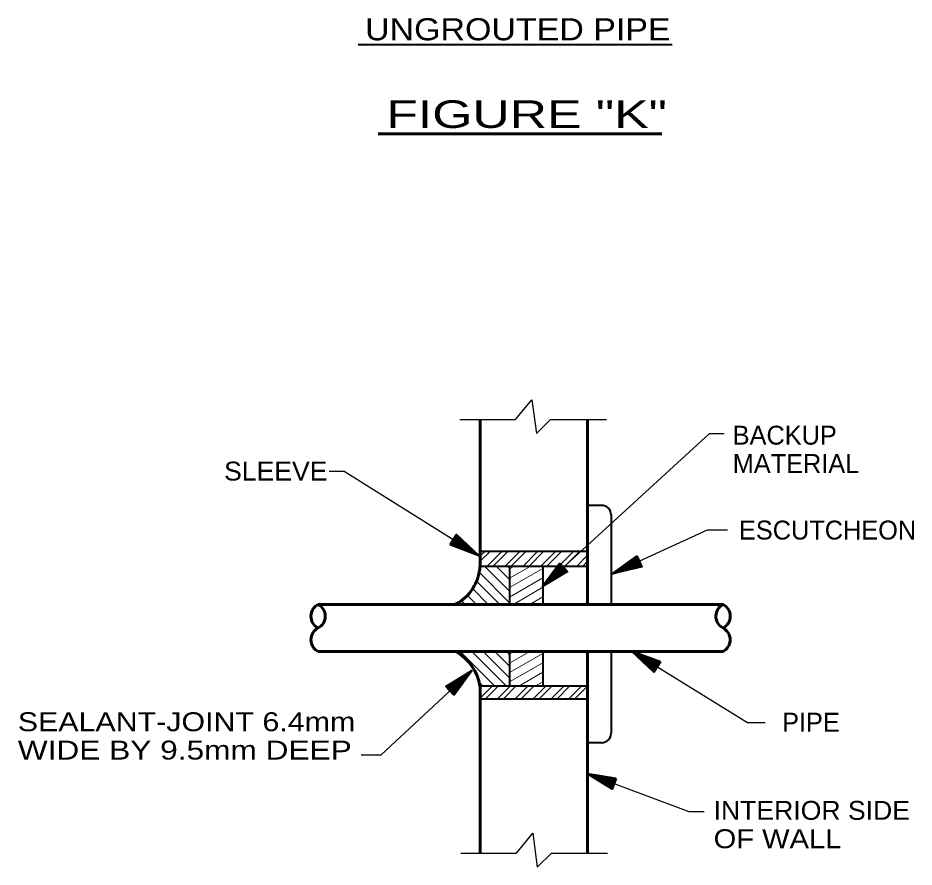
# Model space of a CAD drawing. Extents: x 55 to 190, y 198 to 264.
# Drawn here: x 88.91 to 100.94, y 236.28 to 247.68 of the extents above; entities that cross this region are included whole.
import ezdxf
from ezdxf.enums import TextEntityAlignment as Align

# ---------------------------------------------------------------- set-up
doc = ezdxf.new("R2010")
doc.units = 0
doc.header["$LTSCALE"] = 0.1
doc.layers.add('2', color=7, linetype='Continuous', lineweight=40)

msp = doc.modelspace()

# ---------------------------------------------------------------- linework, layer by layer
at = {"layer": '2'}
for p, q in [((97.6914, 247.3229), (93.4758, 247.3229)), ((96.7418, 241.1372), (96.5548, 241.1372)), ((96.8704, 241.0086), (96.8704, 239.8093)), ((95.094, 240.4649), (94.7625, 240.6959)), ((95.094, 240.4649), (94.7834, 240.7292)), ((95.094, 240.4649), (94.7201, 240.6284)), ((95.094, 240.4649), (94.7315, 240.6477)), ((95.094, 240.4649), (94.7416, 240.6628)), ((94.7514, 240.6789), (95.094, 240.4649)), ((96.5548, 240.5189), (95.1096, 240.5189)), ((95.9504, 240.0479), (96.1941, 240.3482)), ((95.9504, 240.0479), (96.2089, 240.3326)), ((96.8805, 240.2175), (97.2226, 240.4398)), ((96.8805, 240.2175), (97.2326, 240.4194)), ((96.8805, 240.2175), (97.2395, 240.4027)), ((97.2477, 240.3858), (96.8805, 240.2175)), ((96.8805, 240.2175), (97.2556, 240.3673)), ((96.8805, 240.2175), (97.272, 240.3316)), ((96.5548, 240.318), (95.1096, 240.318)), ((95.5067, 240.3173), (95.5067, 239.8032)), ((95.9504, 240.0479), (96.22, 240.3199)), ((96.2322, 240.3069), (95.9504, 240.0479)), ((95.9504, 240.0479), (96.2449, 240.2924)), ((95.9504, 240.0479), (96.2703, 240.2649)), ((95.9528, 240.3173), (95.9528, 239.8032)), ((95.5067, 239.1745), (95.5067, 238.7118)), ((95.9528, 239.1745), (95.9528, 238.7075)), ((96.8704, 239.1766), (96.8704, 238.0781)), ((97.489, 238.9679), (97.1453, 239.1801)), ((97.1453, 239.1801), (97.5086, 238.9988)), ((97.1453, 239.1801), (97.4572, 238.9173)), ((97.1453, 239.1801), (97.4779, 238.9507)), ((97.1453, 239.1801), (97.4985, 238.984)), ((97.1453, 239.1801), (97.5199, 239.0184)), ((95.0011, 238.9203), (94.6654, 238.6885)), ((95.0011, 238.9203), (94.6921, 238.6596)), ((94.7058, 238.6448), (95.0011, 238.9203)), ((95.0011, 238.9203), (94.7188, 238.6311)), ((95.0011, 238.9203), (94.7307, 238.6176)), ((95.0011, 238.9203), (94.7463, 238.6014)), ((96.5548, 238.7075), (95.1096, 238.7075)), ((95.1096, 238.5382), (96.5548, 238.5382)), ((96.7418, 237.9495), (96.5548, 237.9495)), ((96.9117, 237.3986), (96.5529, 237.5317)), ((96.5529, 237.5317), (96.9241, 237.4312)), ((96.5529, 237.5317), (96.8916, 237.3457)), ((96.5529, 237.5317), (96.9048, 237.3807)), ((96.5529, 237.5317), (96.9178, 237.4153)), ((96.5529, 237.5317), (96.931, 237.4513))]:
    msp.add_line(p, q, dxfattribs=at)
at = {"layer": '2', "lineweight": 60}
for p, q in [((93.7425, 246.1291), (97.5506, 246.1291)), ((95.1109, 242.2895), (95.1109, 240.318)), ((96.5548, 242.2895), (96.5548, 239.8066)), ((98.3722, 239.8066), (92.9366, 239.8066)), ((92.9366, 239.1737), (98.3722, 239.1737)), ((96.5548, 239.1737), (96.5548, 236.467)), ((95.1109, 236.467), (95.1109, 238.7075))]:
    msp.add_line(p, q, dxfattribs=at)
at = {"layer": '2', "lineweight": 13}
for p, q in [((95.1091, 240.4525), (95.176, 240.5194)), ((95.1104, 240.3855), (95.2443, 240.5189)), ((95.2033, 240.318), (95.4041, 240.5189)), ((95.2832, 240.318), (95.4842, 240.5189)), ((95.4432, 240.318), (95.6441, 240.5189)), ((95.5234, 240.318), (95.7242, 240.5189)), ((95.6832, 240.318), (95.884, 240.5189)), ((95.7636, 240.318), (95.9642, 240.5189)), ((95.9235, 240.318), (96.124, 240.5189)), ((96.0036, 240.318), (96.2044, 240.5189)), ((96.1634, 240.318), (96.3643, 240.5189)), ((96.2436, 240.318), (96.4444, 240.5189)), ((96.4034, 240.318), (96.5548, 240.4694)), ((96.4836, 240.318), (96.5548, 240.3892)), ((95.5067, 239.8302), (95.0974, 240.2395)), ((95.5067, 239.9852), (95.1739, 240.318)), ((95.5067, 240.1405), (95.3297, 240.3175)), ((95.5067, 240.2958), (95.485, 240.3173)), ((95.5067, 240.1585), (95.7816, 240.3173)), ((95.5067, 240.2852), (95.562, 240.3173)), ((95.5067, 240.0318), (95.9528, 240.2895)), ((95.3774, 239.8048), (95.0617, 240.1199)), ((95.5067, 239.9053), (95.9528, 240.1625)), ((95.2207, 239.8061), (95.0083, 240.0185)), ((95.5496, 239.8032), (95.9528, 240.0363)), ((94.9072, 239.809), (94.8566, 239.8593)), ((95.0638, 239.8077), (94.9395, 239.9318)), ((95.7692, 239.8032), (95.9528, 239.9095)), ((95.3083, 238.7097), (94.8455, 239.1724)), ((95.4618, 238.7112), (95.0001, 239.1729)), ((95.5067, 238.8216), (95.1546, 239.1735)), ((95.5067, 238.9766), (95.3094, 239.1743)), ((95.5067, 239.1317), (95.4639, 239.1745)), ((95.5067, 239.0181), (95.7777, 239.1745)), ((95.5067, 239.1452), (95.5581, 239.1745)), ((95.5067, 238.8917), (95.9528, 239.1491)), ((95.5067, 238.765), (95.9528, 239.0224)), ((95.6319, 238.7104), (95.9528, 238.8957)), ((95.1546, 238.7078), (95.0948, 238.7676)), ((95.8475, 238.7083), (95.9528, 238.7692)), ((95.1096, 238.544), (95.2731, 238.7075)), ((95.1109, 238.7051), (95.113, 238.7075)), ((95.1837, 238.5382), (95.353, 238.7075)), ((95.3438, 238.5382), (95.5131, 238.7075)), ((95.4237, 238.5382), (95.593, 238.7075)), ((95.5837, 238.5382), (95.7531, 238.7075)), ((95.6639, 238.5382), (95.8332, 238.7075)), ((95.8237, 238.5382), (95.993, 238.7075)), ((95.9039, 238.5382), (96.0732, 238.7075)), ((96.0639, 238.5382), (96.2333, 238.7075)), ((96.1439, 238.5382), (96.3132, 238.7075)), ((96.3039, 238.5382), (96.4733, 238.7075)), ((96.3838, 238.5382), (96.5532, 238.7075)), ((96.5439, 238.5382), (96.5548, 238.5488))]:
    msp.add_line(p, q, dxfattribs=at)
at = {"layer": '2', "lineweight": 25}
for points in [[(94.8403, 242.2895), (95.5845, 242.2895), (95.8065, 242.5564), (95.8663, 242.1013), (96.0549, 242.2895), (96.8095, 242.2895)], [(98.3865, 242.0958), (98.1856, 242.0958), (95.9504, 240.0479)], [(93.0839, 241.5968), (93.2866, 241.5968), (95.094, 240.4649)], [(98.4312, 240.8025), (98.161, 240.8025), (96.8805, 240.2175)], [(98.9357, 238.2173), (98.6992, 238.2173), (97.1453, 239.1801)], [(93.5147, 237.7886), (93.7848, 237.7886), (95.0011, 238.9203)], [(98.1187, 237.0229), (97.9181, 237.0229), (96.5529, 237.5317)], [(94.8535, 236.467), (95.5978, 236.467), (95.8197, 236.734), (95.8795, 236.2789), (96.0682, 236.467), (96.8228, 236.467)]]:
    msp.add_lwpolyline(points, dxfattribs=at)
at = {"layer": '2'}
for points in [[(94.7093, 240.611), (94.7953, 240.7477), (95.094, 240.4649)], [(94.7093, 240.611), (95.094, 240.4649), (94.7728, 240.7131)], [(97.2141, 240.4583), (97.281, 240.3114), (96.8805, 240.2175)], [(97.2141, 240.4583), (96.8805, 240.2175), (97.2644, 240.3493)], [(96.1809, 240.3625), (96.2841, 240.2495), (95.9504, 240.0479)], [(96.1809, 240.3625), (95.9504, 240.0479), (96.2579, 240.2786)], [(97.5308, 239.0359), (97.4453, 238.8988), (97.1453, 239.1801)], [(97.5308, 239.0359), (97.1453, 239.1801), (97.4678, 238.9335)], [(94.7603, 238.5864), (94.6505, 238.7049), (95.0011, 238.9203)], [(94.7603, 238.5864), (95.0011, 238.9203), (94.6783, 238.6742)], [(96.9379, 237.4695), (96.8841, 237.3264), (96.5529, 237.5317)], [(96.9379, 237.4695), (96.5529, 237.5317), (96.8984, 237.3629)]]:
    msp.add_lwpolyline(points, dxfattribs=at)
for centre, start, end in [((96.7418, 241.0086), 0, 90), ((96.7418, 238.0781), 270, 0)]:
    msp.add_arc(centre, 0.1286, start, end, dxfattribs=at)
at = {"layer": '2', "lineweight": 60}
for centre, radius, start, end in [((94.5012, 240.3504), 0.6092, 297.50967, 356.96377), ((93.0187, 239.6482), 0.1783, 117.38482, 241.91503), ((92.8546, 239.6482), 0.1783, 298.08497, 62.61518), ((98.4543, 239.6482), 0.1783, 117.38482, 241.91503), ((98.2902, 239.6482), 0.1783, 298.08497, 62.61518), ((93.0205, 239.3319), 0.1791, 117.91829, 242.08171), ((98.2884, 239.3319), 0.1791, 297.91829, 62.08171), ((94.4693, 238.6072), 0.648, 8.91205, 60.69235)]:
    msp.add_arc(centre, radius, start, end, dxfattribs=at)

# ---------------------------------------------------------------- texts
at = {"layer": '2'}
for s, height, width, p in [('UNGROUTED PIPE', 0.2963, 1.15, (93.5673, 247.3832)), ('SLEEVE', 0.254, 1.05, (91.675, 241.47)), ('SEALANT-JOINT 6.4mm', 0.254, 1.2, (88.9062, 238.104)), ('WIDE BY 9.5mm DEEP', 0.254, 1.25, (88.9062, 237.723)), ('INTERIOR SIDE', 0.254, 1.05, (98.2457, 236.9137)), ('OF WALL', 0.254, 1.15, (98.2457, 236.5327))]:
    msp.add_text(s, height=height, dxfattribs=dict(at, width=width)).set_placement(p)
at = {"layer": '2', "width": 1.4}
msp.add_text('FIGURE "K"', height=0.3704, dxfattribs=at).set_placement((95.7361, 246.2061), align=Align.CENTER)
at = {"layer": '2'}
for s, p in [('BACKUP', (98.5021, 241.9529)), ('MATERIAL', (98.5021, 241.5719)), ('ESCUTCHEON', (98.5862, 240.6784)), ('PIPE', (99.1649, 238.0977))]:
    msp.add_text(s, height=0.254, dxfattribs=at).set_placement(p)

doc.saveas('drawing.dxf')
